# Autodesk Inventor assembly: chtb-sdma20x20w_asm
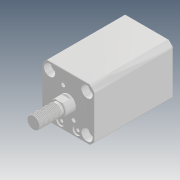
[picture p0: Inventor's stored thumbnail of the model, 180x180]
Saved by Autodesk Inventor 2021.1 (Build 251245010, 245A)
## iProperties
Company: Microsoft
Created: 2018-05
Part Number: chtb-sdma20x20w_asm
Description: STEP AP214
Document SubType Name: Assembly
Designer: user
Title: chtb-sdma20x20w_asm.STEP
Author: Windows
Revision Number: ÈÎºÎ
Sending System: SolidWorks 2015
Preprocessor: SwSTEP 2.0
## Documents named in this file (4)
- D:\Vault_2016\Projekty\Clamptek\Hydraulic\CHTB\CHTB-20\Inventor\CHTB-SDMA20x20W\chtb-sdma20x20w_asm.iam
- D:\Vault_2016\Projekty\Clamptek\Hydraulic\CHTB\CHTB-20\Inventor\CHTB-SDMA20x20W\CHTB-SDMA20X20NBT.ipt
- D:\Vault_2016\Projekty\Clamptek\Hydraulic\CHTB\CHTB-20\Inventor\CHTB-SDMA20x20W\CHTB-SDMA20X20WHSG.ipt
- D:\Vault_2016\Projekty\Clamptek\Hydraulic\CHTB\CHTB-20\Inventor\CHTB-SDMA20x20W\QG_3.ipt
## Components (3 placed, 3 different names)
1. CHTB-SDMA20X20NBT_1
2. CHTB-SDMA20X20WHSG_2
3. QG_3_3
